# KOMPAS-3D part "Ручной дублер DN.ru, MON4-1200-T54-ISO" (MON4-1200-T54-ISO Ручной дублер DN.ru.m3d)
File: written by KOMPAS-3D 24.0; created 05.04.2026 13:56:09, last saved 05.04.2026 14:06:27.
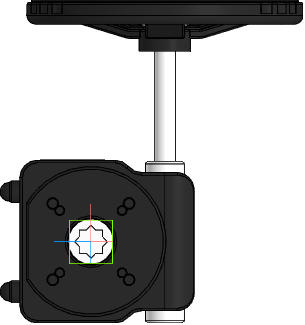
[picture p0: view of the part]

Document properties: Автор: R2D2; Полное имя файла: E:\Работа\Зайцев\Аксессуары для пневмоприводов\Ручной дублер DN.ru\MON4-1200-T54-ISO Ручной дублер DN.ru\MON4-1200-T54-ISO Ручной дублер DN.ru.m3d

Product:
- Part/product: Ручной дублер DN.ru  | designation MON4-1200-T54-ISO
    Масса: 13.7
    Раздел спецификации: Прочие изделия
    Примечание: D290-00339

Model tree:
1. Операция без истории:1

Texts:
  MON4-1200-T54-ISO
